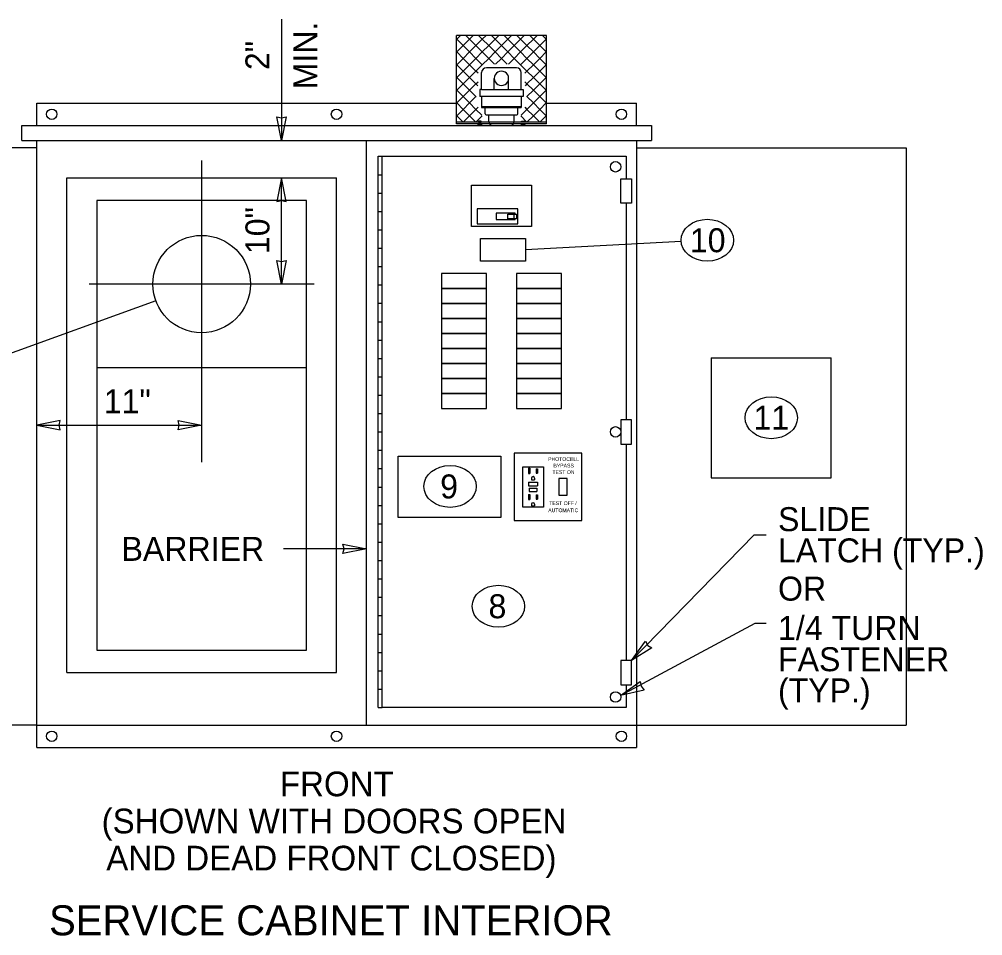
# Model space of a CAD drawing. Extents: x 99862 to 103680, y 99470 to 105076.
# Drawn here: x 100953 to 101596, y 100630 to 101241 of the extents above; entities that cross this region are included whole.
import ezdxf

# ---------------------------------------------------------------- set-up
doc = ezdxf.new("R2010")
doc.units = 0
for name, color, linetype in [('Level 1', 7, 'Continuous'), ('Level 15', 7, 'Continuous'), ('Level 20', 7, 'Continuous'), ('Level 34', 7, 'Continuous'), ('Level 40', 7, 'Continuous')]:
    doc.layers.add(name, color=color, linetype=linetype)

msp = doc.modelspace()

# ---------------------------------------------------------------- linework, layer by layer
at = {"layer": 'Level 1'}
for p, q in [((101244.91, 101172.75), (101244.91, 101230.51)), ((101304.91, 101230.51), (101244.91, 101230.51)), ((101244.91, 101228.28), (101245.13, 101228.06)), ((101245.13, 101228.06), (101244.91, 101227.84)), ((101245.13, 101228.06), (101247.58, 101230.51)), ((101249.38, 101223.8), (101245.13, 101228.06)), ((101253.64, 101228.06), (101249.38, 101223.8)), ((101251.19, 101230.51), (101253.64, 101228.06)), ((101256.09, 101230.51), (101253.64, 101228.06)), ((101253.64, 101228.06), (101257.89, 101223.8)), ((101257.89, 101223.8), (101262.15, 101228.06)), ((101262.15, 101228.06), (101259.7, 101230.51)), ((101264.6, 101230.51), (101262.15, 101228.06)), ((101262.15, 101228.06), (101266.4, 101223.8)), ((101266.4, 101223.8), (101270.66, 101228.06)), ((101270.66, 101228.06), (101268.2, 101230.51)), ((101273.11, 101230.51), (101270.66, 101228.06)), ((101270.66, 101228.06), (101274.91, 101223.8)), ((101274.91, 101223.8), (101279.16, 101228.06)), ((101279.16, 101228.06), (101276.71, 101230.51)), ((101281.62, 101230.51), (101279.16, 101228.06)), ((101279.16, 101228.06), (101283.42, 101223.8)), ((101283.42, 101223.8), (101287.67, 101228.06)), ((101287.67, 101228.06), (101285.22, 101230.51)), ((101290.12, 101230.51), (101287.67, 101228.06)), ((101287.67, 101228.06), (101291.93, 101223.8)), ((101291.93, 101223.8), (101296.18, 101228.06)), ((101293.73, 101230.51), (101296.18, 101228.06)), ((101296.18, 101228.06), (101298.63, 101230.51)), ((101296.18, 101228.06), (101300.44, 101223.8)), ((101300.44, 101223.8), (101304.69, 101228.06)), ((101304.69, 101228.06), (101302.24, 101230.51)), ((101304.91, 101228.28), (101304.69, 101228.06)), ((101304.69, 101228.06), (101304.91, 101227.84)), ((101304.91, 101172.75), (101304.91, 101230.51)), ((101245.13, 101219.55), (101249.38, 101223.8)), ((101249.38, 101223.8), (101253.64, 101219.55)), ((101257.89, 101223.8), (101253.64, 101219.55)), ((101262.15, 101219.55), (101257.89, 101223.8)), ((101266.4, 101223.8), (101262.15, 101219.55)), ((101270.66, 101219.55), (101266.4, 101223.8)), ((101274.91, 101223.8), (101270.66, 101219.55)), ((101279.16, 101219.55), (101274.91, 101223.8)), ((101283.42, 101223.8), (101279.16, 101219.55)), ((101287.67, 101219.55), (101283.42, 101223.8)), ((101291.93, 101223.8), (101287.67, 101219.55)), ((101296.18, 101219.55), (101291.93, 101223.8)), ((101300.44, 101223.8), (101296.18, 101219.55)), ((101304.69, 101219.55), (101300.44, 101223.8)), ((101244.91, 101219.77), (101245.13, 101219.55)), ((101245.13, 101219.55), (101244.91, 101219.33)), ((101249.38, 101215.3), (101245.13, 101219.55)), ((101245.13, 101211.04), (101249.38, 101215.3)), ((101253.64, 101219.55), (101249.38, 101215.3)), ((101249.38, 101215.3), (101253.64, 101211.04)), ((101253.64, 101219.55), (101257.89, 101215.3)), ((101257.89, 101215.3), (101253.64, 101211.04)), ((101257.89, 101215.3), (101262.15, 101219.55)), ((101262.15, 101211.04), (101257.89, 101215.3)), ((101262.15, 101219.55), (101266.4, 101215.3)), ((101266.4, 101215.3), (101262.15, 101211.04)), ((101266.4, 101215.3), (101270.66, 101219.55)), ((101270.28, 101211.42), (101266.4, 101215.3)), ((101270.66, 101219.55), (101274.91, 101215.3)), ((101274.91, 101215.3), (101271.04, 101211.42)), ((101274.91, 101215.3), (101279.16, 101219.55)), ((101278.78, 101211.42), (101274.91, 101215.3)), ((101279.16, 101219.55), (101283.42, 101215.3)), ((101283.42, 101215.3), (101279.54, 101211.42)), ((101283.42, 101215.3), (101287.67, 101219.55)), ((101287.67, 101211.04), (101283.42, 101215.3)), ((101287.67, 101219.55), (101291.93, 101215.3)), ((101291.93, 101215.3), (101287.67, 101211.04)), ((101291.93, 101215.3), (101296.18, 101219.55)), ((101296.18, 101211.04), (101291.93, 101215.3)), ((101296.18, 101219.55), (101300.44, 101215.3)), ((101300.44, 101215.3), (101296.18, 101211.04)), ((101300.44, 101215.3), (101304.69, 101219.55)), ((101304.69, 101211.04), (101300.44, 101215.3)), ((101304.91, 101219.77), (101304.69, 101219.55)), ((101304.69, 101219.55), (101304.91, 101219.33)), ((101244.91, 101211.26), (101245.13, 101211.04)), ((101245.13, 101211.04), (101244.91, 101210.82)), ((101249.38, 101206.79), (101245.13, 101211.04)), ((101253.64, 101211.04), (101249.38, 101206.79)), ((101253.64, 101211.04), (101257.89, 101206.79)), ((101257.89, 101206.79), (101262.15, 101211.04)), ((101262.15, 101211.04), (101262.36, 101210.83)), ((101284.94, 101209.01), (101264.88, 101209.01)), ((101287.46, 101210.82), (101287.67, 101211.04)), ((101287.67, 101211.04), (101291.93, 101206.79)), ((101291.93, 101206.79), (101296.18, 101211.04)), ((101296.18, 101211.04), (101300.44, 101206.79)), ((101300.44, 101206.79), (101304.69, 101211.04)), ((101304.91, 101211.26), (101304.69, 101211.04)), ((101304.69, 101211.04), (101304.91, 101210.82)), ((101244.91, 101202.75), (101245.13, 101202.53)), ((101245.13, 101202.53), (101244.91, 101202.31)), ((101245.13, 101202.53), (101249.38, 101206.79)), ((101249.38, 101198.28), (101245.13, 101202.53)), ((101249.38, 101206.79), (101253.64, 101202.53)), ((101253.64, 101202.53), (101249.38, 101198.28)), ((101257.89, 101206.79), (101253.64, 101202.53)), ((101253.64, 101202.53), (101257.89, 101198.28)), ((101259.27, 101205.41), (101257.89, 101206.79)), ((101261.67, 101194.58), (101261.67, 101205.81)), ((101270.1, 101194.58), (101270.1, 101201.96)), ((101279.72, 101194.58), (101279.72, 101201.96)), ((101288.15, 101194.58), (101288.15, 101205.81)), ((101291.93, 101206.79), (101290.55, 101205.41)), ((101296.18, 101202.53), (101291.93, 101206.79)), ((101291.93, 101198.28), (101296.18, 101202.53)), ((101300.44, 101206.79), (101296.18, 101202.53)), ((101296.18, 101202.53), (101300.44, 101198.28)), ((101304.69, 101202.53), (101300.44, 101206.79)), ((101300.44, 101198.28), (101304.69, 101202.53)), ((101304.91, 101202.75), (101304.69, 101202.53)), ((101304.69, 101202.53), (101304.91, 101202.31)), ((101245.13, 101194.02), (101249.38, 101198.28)), ((101249.38, 101198.28), (101253.64, 101194.02)), ((101257.89, 101198.28), (101253.64, 101194.02)), ((101257.89, 101198.28), (101259.27, 101199.65)), ((101259.19, 101196.98), (101257.89, 101198.28)), ((101261.67, 101194.58), (101260.47, 101194.58)), ((101260.47, 101194.58), (101260.47, 101189.76)), ((101261.67, 101194.58), (101288.15, 101194.58)), ((101288.15, 101194.58), (101289.35, 101194.58)), ((101289.35, 101194.58), (101289.35, 101189.76)), ((101290.55, 101199.65), (101291.93, 101198.28)), ((101291.93, 101198.28), (101290.63, 101196.98)), ((101296.18, 101194.02), (101291.93, 101198.28)), ((101300.44, 101198.28), (101296.18, 101194.02)), ((101304.69, 101194.02), (101300.44, 101198.28)), ((101244.91, 101194.25), (101245.13, 101194.02)), ((101245.13, 101194.02), (101244.91, 101193.8)), ((101249.38, 101189.77), (101245.13, 101194.02)), ((101245.13, 101185.52), (101249.38, 101189.77)), ((101253.64, 101194.02), (101249.38, 101189.77)), ((101249.38, 101189.77), (101253.64, 101185.52)), ((101253.64, 101194.02), (101257.89, 101189.77)), ((101257.89, 101189.77), (101253.64, 101185.52)), ((101257.89, 101189.77), (101258.06, 101189.94)), ((101258.06, 101189.6), (101257.89, 101189.77)), ((101289.35, 101189.76), (101260.47, 101189.76)), ((101261.67, 101189.76), (101261.67, 101182.54)), ((101288.15, 101189.76), (101288.15, 101182.54)), ((101291.76, 101189.94), (101291.93, 101189.77)), ((101291.93, 101189.77), (101291.76, 101189.6)), ((101291.93, 101189.77), (101296.18, 101194.02)), ((101296.18, 101185.52), (101291.93, 101189.77)), ((101296.18, 101194.02), (101300.44, 101189.77)), ((101300.44, 101189.77), (101296.18, 101185.52)), ((101300.44, 101189.77), (101304.69, 101194.02)), ((101304.69, 101185.52), (101300.44, 101189.77)), ((101304.91, 101194.25), (101304.69, 101194.02)), ((101304.69, 101194.02), (101304.91, 101193.8)), ((101244.91, 101185.74), (101245.13, 101185.52)), ((101245.13, 101185.52), (101244.91, 101185.3)), ((101249.38, 101181.26), (101245.13, 101185.52)), ((101253.64, 101185.52), (101249.38, 101181.26)), ((101253.64, 101185.52), (101257.89, 101181.26)), ((101257.89, 101181.26), (101259.27, 101182.64)), ((101261.67, 101183.14), (101288.15, 101183.14)), ((101261.67, 101182.54), (101288.15, 101182.54)), ((101264.08, 101178.33), (101264.08, 101182.54)), ((101285.74, 101178.33), (101285.74, 101182.54)), ((101290.55, 101182.64), (101291.93, 101181.26)), ((101291.93, 101181.26), (101296.18, 101185.52)), ((101296.18, 101185.52), (101300.44, 101181.26)), ((101300.44, 101181.26), (101304.69, 101185.52)), ((101304.91, 101185.74), (101304.69, 101185.52)), ((101304.69, 101185.52), (101304.91, 101185.3)), ((101244.91, 101177.23), (101245.13, 101177.01)), ((101245.13, 101177.01), (101244.91, 101176.79)), ((101245.13, 101177.01), (101249.38, 101181.26)), ((101249.38, 101172.75), (101245.13, 101177.01)), ((101249.38, 101181.26), (101253.64, 101177.01)), ((101253.64, 101177.01), (101249.38, 101172.75)), ((101257.89, 101181.26), (101253.64, 101177.01)), ((101253.64, 101177.01), (101257.89, 101172.75)), ((101261.86, 101177.3), (101257.89, 101181.26)), ((101257.89, 101172.75), (101262.04, 101176.9)), ((101264.68, 101177.73), (101285.14, 101177.73)), ((101266.49, 101172.92), (101266.49, 101177.73)), ((101283.33, 101172.92), (101283.33, 101177.73)), ((101287.78, 101176.9), (101291.93, 101172.75)), ((101291.93, 101181.26), (101287.96, 101177.3)), ((101296.18, 101177.01), (101291.93, 101181.26)), ((101291.93, 101172.75), (101296.18, 101177.01)), ((101300.44, 101181.26), (101296.18, 101177.01)), ((101296.18, 101177.01), (101300.44, 101172.75)), ((101304.69, 101177.01), (101300.44, 101181.26)), ((101300.44, 101172.75), (101304.69, 101177.01)), ((101304.91, 101177.23), (101304.69, 101177.01)), ((101304.69, 101177.01), (101304.91, 101176.79)), ((101304.91, 101172.75), (101244.91, 101172.75)), ((101244.91, 101171.71), (101244.91, 101172.65)), ((101304.91, 101172.65), (101244.91, 101172.65)), ((101304.91, 101171.71), (101244.91, 101171.71)), ((101268.89, 101170.51), (101280.93, 101170.51)), ((101304.91, 101171.71), (101304.91, 101172.65)), ((101283.11, 101111.36), (101283.11, 101108.3)), ((101144.91, 101008.88), (101004.91, 101008.88)), ((101289.08, 100915.88), (101289.08, 100942.88)), ((101289.08, 100942.88), (101302.87, 100942.88)), ((101292.92, 100941.77), (101293.79, 100941.77)), ((101292.92, 100941.77), (101292.92, 100938.31)), ((101292.92, 100938.31), (101293.79, 100938.31)), ((101293.79, 100941.77), (101293.79, 100938.31)), ((101298.15, 100941.42), (101298.15, 100938.6)), ((101298.15, 100941.42), (101299.02, 100941.42)), ((101298.15, 100938.6), (101299.02, 100938.6)), ((101299.02, 100941.42), (101299.02, 100938.6)), ((101302.87, 100942.88), (101302.87, 100915.88)), ((101292.98, 100932.65), (101298.98, 100932.65)), ((101292.98, 100932.65), (101292.98, 100930.2)), ((101294.9, 100935.17), (101294.9, 100934.15)), ((101294.9, 100934.15), (101297.03, 100934.15)), ((101297.03, 100935.17), (101297.03, 100934.15)), ((101298.98, 100932.65), (101298.98, 100930.2)), ((101292.98, 100930.2), (101298.98, 100930.2)), ((101293.48, 100928.63), (101293.48, 100926.23)), ((101293.48, 100928.63), (101298.44, 100928.63)), ((101293.48, 100926.23), (101298.44, 100926.23)), ((101298.44, 100928.63), (101298.44, 100926.23)), ((101292.92, 100924.4), (101293.79, 100924.4)), ((101292.92, 100924.4), (101292.92, 100920.94)), ((101292.92, 100920.94), (101293.79, 100920.94)), ((101293.79, 100924.4), (101293.79, 100920.94)), ((101298.15, 100924.05), (101298.15, 100921.23)), ((101298.15, 100924.05), (101299.02, 100924.05)), ((101298.15, 100921.23), (101299.02, 100921.23)), ((101299.02, 100924.05), (101299.02, 100921.23)), ((101302.87, 100915.88), (101289.08, 100915.88)), ((101294.9, 100917.8), (101294.9, 100916.78)), ((101294.9, 100916.78), (101297.03, 100916.78)), ((101297.03, 100917.8), (101297.03, 100916.78))]:
    msp.add_line(p, q, dxfattribs=at)
for points in [[(101254.91, 101130.61), (101294.91, 101130.61), (101294.91, 101103.11), (101254.91, 101103.11)], [(101354.44, 101134.84), (101361.68, 101134.84), (101361.68, 101118.69), (101354.44, 101118.69)], [(101004.91, 100820.51), (101144.91, 100820.51), (101144.91, 101120.51), (101004.91, 101120.51)], [(101258.66, 101104.83), (101285.85, 101104.83), (101285.85, 101114.83), (101258.66, 101114.83)], [(101284.87, 101108.3), (101279.11, 101108.3), (101279.11, 101111.36), (101284.87, 101111.36)], [(101234.91, 101061.66), (101264.91, 101061.66), (101264.91, 101071.66), (101234.91, 101071.66)], [(101284.91, 101061.66), (101314.91, 101061.66), (101314.91, 101071.66), (101284.91, 101071.66)], [(101234.91, 101051.66), (101264.91, 101051.66), (101264.91, 101061.66), (101234.91, 101061.66)], [(101284.91, 101051.66), (101314.91, 101051.66), (101314.91, 101061.66), (101284.91, 101061.66)], [(101234.91, 101041.66), (101264.91, 101041.66), (101264.91, 101051.66), (101234.91, 101051.66)], [(101284.91, 101041.66), (101314.91, 101041.66), (101314.91, 101051.66), (101284.91, 101051.66)], [(101234.91, 101031.66), (101264.91, 101031.66), (101264.91, 101041.66), (101234.91, 101041.66)], [(101284.91, 101031.66), (101314.91, 101031.66), (101314.91, 101041.66), (101284.91, 101041.66)], [(101234.91, 101021.66), (101264.91, 101021.66), (101264.91, 101031.66), (101234.91, 101031.66)], [(101284.91, 101021.66), (101314.91, 101021.66), (101314.91, 101031.66), (101284.91, 101031.66)], [(101234.91, 101011.66), (101264.91, 101011.66), (101264.91, 101021.66), (101234.91, 101021.66)], [(101284.91, 101011.66), (101314.91, 101011.66), (101314.91, 101021.66), (101284.91, 101021.66)], [(101234.91, 101001.66), (101264.91, 101001.66), (101264.91, 101011.66), (101234.91, 101011.66)], [(101284.91, 101001.66), (101314.91, 101001.66), (101314.91, 101011.66), (101284.91, 101011.66)], [(101234.91, 100991.66), (101264.91, 100991.66), (101264.91, 101001.66), (101234.91, 101001.66)], [(101284.91, 100991.66), (101314.91, 100991.66), (101314.91, 101001.66), (101284.91, 101001.66)], [(101234.91, 100981.66), (101264.91, 100981.66), (101264.91, 100991.66), (101234.91, 100991.66)], [(101284.91, 100981.66), (101314.91, 100981.66), (101314.91, 100991.66), (101284.91, 100991.66)], [(101354.44, 100958), (101361.68, 100958), (101361.68, 100974.15), (101354.44, 100974.15)], [(101283.48, 100906.88), (101328.48, 100906.88), (101328.48, 100951.88), (101283.48, 100951.88)], [(101313.14, 100934.91), (101313.14, 100923.85), (101318.81, 100923.85), (101318.81, 100934.91)], [(101354.44, 100797.3), (101361.68, 100797.3), (101361.68, 100813.46), (101354.44, 100813.46)]]:
    msp.add_lwpolyline(points, close=True, dxfattribs=at)
msp.add_lwpolyline([(101283.98, 101111.36), (101283.98, 101111.91), (101271.38, 101111.91), (101271.38, 101107.75), (101283.98, 101107.75), (101283.98, 101108.3)], dxfattribs=at)
for centre, radius in [((101351.06, 101142.94), 3.5), ((101074.91, 101064.69), 32.5), ((101351.06, 100966.07), 3.5), ((101351.06, 100789.2), 3.5)]:
    msp.add_circle(centre, radius, dxfattribs=at)
for centre, radius, start, end in [((101264.88, 101205.81), 3.21, 90, 180), ((101284.94, 101205.81), 3.21, 0, 90), ((101274.91, 101201.96), 4.81, 359.99971, 180), ((101274.91, 101201.96), 4.81, 180, 0.00029), ((101264.68, 101178.33), 0.602, 180, 270), ((101285.14, 101178.33), 0.602, 270, 0), ((101268.89, 101172.92), 2.41, 180, 270), ((101280.93, 101172.92), 2.41, 270, 0), ((101295.97, 100935.17), 1.06, 360, 180), ((101295.97, 100917.8), 1.06, 360, 180)]:
    msp.add_arc(centre, radius, start, end, dxfattribs=at)
at = {"layer": 'Level 15'}
for p, q in [((101128.12, 101241.38), (101128.12, 101160.51)), ((100954.91, 101170.51), (101374.91, 101170.51)), ((100954.91, 101160.51), (100954.91, 101170.51)), ((101374.91, 101170.51), (101374.91, 101160.51)), ((100954.91, 101160.51), (101374.91, 101160.51)), ((101074.91, 101147.19), (101074.91, 100945.89)), ((101128.12, 101064.69), (101128.12, 101135.51)), ((101394.77, 101093.03), (101290.89, 101087.52)), ((101149.91, 101064.69), (100999.91, 101064.69)), ((101044.36, 101053.6), (100871.74, 100990.88)), ((101414.91, 101015.51), (101414.91, 100935.51)), ((101414.91, 101015.51), (101494.91, 101015.51)), ((101494.91, 100935.51), (101494.91, 101015.51)), ((100964.91, 100970.5), (101074.91, 100970.5)), ((101414.91, 100935.51), (101494.91, 100935.51)), ((101361.68, 100813.46), (101443.4, 100897.44)), ((101443.4, 100897.44), (101451.4, 100897.44)), ((101184.91, 100888.03), (101129.41, 100888.03)), ((101354.4, 100790.25), (101444.2, 100838.41)), ((101444.2, 100838.41), (101451.4, 100838.41))]:
    msp.add_line(p, q, dxfattribs=at)
for points in [[(101128.12, 101160.51), (101125.04, 101176.24), (101128.12, 101175.51), (101131.21, 101176.24)], [(101128.12, 101135.51), (101125.04, 101119.79), (101128.12, 101120.51), (101131.21, 101119.79)], [(101128.12, 101064.69), (101125.04, 101080.42), (101128.12, 101079.69), (101131.21, 101080.42)], [(100964.91, 100970.5), (100980.63, 100967.42), (100979.91, 100970.5), (100980.63, 100973.59)], [(101074.91, 100970.5), (101059.18, 100967.42), (101059.91, 100970.5), (101059.18, 100973.59)], [(101184.91, 100888.03), (101169.18, 100884.95), (101169.91, 100888.03), (101169.18, 100891.12)], [(101361.68, 100813.46), (101371.09, 100826.42), (101372.66, 100823.67), (101375.29, 100821.91)], [(101354.4, 100790.25), (101367.5, 100799.48), (101368.09, 100796.37), (101370.01, 100793.85)]]:
    msp.add_lwpolyline(points, close=True, dxfattribs=at)
for centre in [(100974.91, 101178.01), (101164.91, 101178.01), (101354.91, 101178.01), (100974.91, 100763.01), (101164.91, 100763.01), (101354.91, 100763.01)]:
    msp.add_circle(centre, 3.5, dxfattribs=at)
at = {"layer": 'Level 20'}
for centre in [(101412.23, 101093.95), (101454.91, 100975.51), (101240.63, 100929.69), (101272.87, 100849.75)]:
    msp.add_ellipse(centre, major_axis=(-17.5, 0), ratio=0.8, dxfattribs=at)
at = {"layer": 'Level 34'}
for points in [[(101260.89, 101095.12), (101290.89, 101095.12), (101290.89, 101079.92), (101260.89, 101079.92)], [(101205.99, 100949.83), (101274.58, 100949.83), (101274.58, 100908.93), (101205.99, 100908.93)]]:
    msp.add_lwpolyline(points, close=True, dxfattribs=at)
at = {"layer": 'Level 40'}
for p, q in [((100964.91, 101185.51), (101244.91, 101185.51)), ((100964.91, 101170.51), (100964.91, 101185.51)), ((101304.91, 101185.51), (101364.91, 101185.51)), ((101364.91, 101170.51), (101364.91, 101185.51)), ((100964.91, 101170.51), (101364.91, 101170.51)), ((100964.91, 100755.51), (100964.91, 101160.51)), ((101184.91, 100770.51), (101184.91, 101160.51)), ((101364.91, 101160.51), (101364.91, 100755.51)), ((100964.91, 101155.51), (100744.91, 101155.51)), ((101192.75, 100782.2), (101192.75, 101149.94)), ((101192.75, 101149.94), (101195.23, 101149.94)), ((101195.23, 100782.2), (101195.23, 101149.94)), ((101195.23, 101149.94), (101358.06, 101149.94)), ((101358.06, 101149.94), (101358.06, 101134.84)), ((101364.91, 101155.51), (101544.91, 101155.51)), ((101544.91, 101155.51), (101544.91, 100770.51)), ((101192.75, 101137.68), (101195.23, 101137.68)), ((100984.91, 100805.51), (100984.91, 101135.51)), ((100984.91, 101135.51), (101164.91, 101135.51)), ((101164.91, 100805.51), (101164.91, 101135.51)), ((101192.75, 101125.43), (101195.23, 101125.43)), ((101358.06, 101118.69), (101358.06, 100974.15)), ((101192.75, 101113.17), (101195.23, 101113.17)), ((101192.75, 101100.91), (101195.23, 101100.91)), ((101192.75, 101088.65), (101195.23, 101088.65)), ((101192.75, 101076.39), (101195.23, 101076.39)), ((101192.75, 101064.14), (101195.23, 101064.14)), ((101192.75, 101051.88), (101195.23, 101051.88)), ((101192.75, 101039.62), (101195.23, 101039.62)), ((101192.75, 101027.36), (101195.23, 101027.36)), ((101192.75, 101015.1), (101195.23, 101015.1)), ((101192.75, 101002.85), (101195.23, 101002.85)), ((101192.75, 100990.59), (101195.23, 100990.59)), ((101192.75, 100978.33), (101195.23, 100978.33)), ((101192.75, 100966.07), (101195.23, 100966.07)), ((101358.06, 100958), (101358.06, 100813.46)), ((101192.75, 100953.81), (101195.23, 100953.81)), ((101192.75, 100941.56), (101195.23, 100941.56)), ((101192.75, 100929.3), (101195.23, 100929.3)), ((101192.75, 100917.04), (101195.23, 100917.04)), ((101192.75, 100904.78), (101195.23, 100904.78)), ((101192.75, 100892.52), (101195.23, 100892.52)), ((101192.75, 100880.27), (101195.23, 100880.27)), ((101192.75, 100868.01), (101195.23, 100868.01)), ((101192.75, 100855.75), (101195.23, 100855.75)), ((101192.75, 100843.49), (101195.23, 100843.49)), ((101192.75, 100831.23), (101195.23, 100831.23)), ((101192.75, 100818.98), (101195.23, 100818.98)), ((100984.91, 100805.51), (101164.91, 100805.51)), ((101192.75, 100806.72), (101195.23, 100806.72)), ((101358.06, 100797.3), (101358.06, 100782.2)), ((101192.75, 100794.46), (101195.23, 100794.46)), ((101192.75, 100782.2), (101195.23, 100782.2)), ((101358.06, 100782.2), (101195.23, 100782.2)), ((100964.91, 100770.51), (100744.91, 100770.51)), ((100964.91, 100770.51), (101364.91, 100770.51)), ((101364.91, 100770.51), (101544.91, 100770.51)), ((100964.91, 100755.51), (101364.91, 100755.51))]:
    msp.add_line(p, q, dxfattribs=at)
for points in [[(101261.81, 101170.75), (101261.81, 101170.51), (101259.13, 101170.51), (101259.13, 101170.75)], [(101261.79, 101170.92), (101261.79, 101170.75), (101259.16, 101170.75), (101259.16, 101170.92)], [(101261.45, 101172.68), (101261.45, 101173.45), (101259.49, 101173.45), (101259.49, 101172.68)], [(101261.45, 101170.92), (101261.45, 101171.71), (101259.49, 101171.71), (101259.49, 101170.92)], [(101288, 101170.75), (101288, 101170.51), (101290.69, 101170.51), (101290.69, 101170.75)], [(101288.03, 101170.92), (101288.03, 101170.75), (101290.66, 101170.75), (101290.66, 101170.92)], [(101288.36, 101172.68), (101288.36, 101173.45), (101290.33, 101173.45), (101290.33, 101172.68)], [(101288.36, 101170.92), (101288.36, 101171.71), (101290.33, 101171.71), (101290.33, 101170.92)]]:
    msp.add_lwpolyline(points, close=True, dxfattribs=at)

# ---------------------------------------------------------------- texts
at = {"layer": 'Level 20'}
for s, rotation, p in [('MIN.', 90, (101152.12, 101194.65)), ('2"', 90, (101120.12, 101207.47)), ('10"', 90, (101120.12, 101084.69)), ('11"', 360, (101009.61, 100978.5)), ('BARRIER', 360, (101021.47, 100880.03))]:
    msp.add_text(s, height=16, rotation=rotation, dxfattribs=at).set_placement(p)
for s, height, p in [('10', 16, (101400.6, 101085.95)), ('11', 16, (101443.04, 100967.51)), ('9', 16, (101234.04, 100921.69)), ('SLIDE', 16, (101459.4, 100899.86)), ('LATCH (TYP.)', 16, (101459.4, 100879.03)), ('OR', 16, (101459.4, 100853.5)), ('8', 16, (101266.28, 100841.75)), ('1/4 TURN', 16, (101459.4, 100827.24)), ('FASTENER', 16, (101459.4, 100806.41)), ('(TYP.)', 16, (101459.4, 100785.58)), ('FRONT', 16.5, (101127.09, 100722.96)), ('(SHOWN WITH DOORS OPEN', 16.5, (101008.18, 100698.21)), ('AND DEAD FRONT CLOSED)', 16.5, (101011.29, 100673.46)), ('SERVICE CABINET INTERIOR', 20, (100973.12, 100630.21))]:
    msp.add_text(s, height=height, dxfattribs=at).set_placement(p)
at = {"layer": 'Level 40'}
for s, p in [('PHOTOCELL', (101306.03, 100946.71)), ('BYPASS', (101309.57, 100942.36)), ('TEST ON', (101308.92, 100938.02)), ('TEST OFF /', (101306.76, 100917.24)), ('AUTOMATIC', (101306.11, 100912.51))]:
    msp.add_text(s, height=2.467, rotation=360, dxfattribs=at).set_placement(p)

doc.saveas('drawing.dxf')
